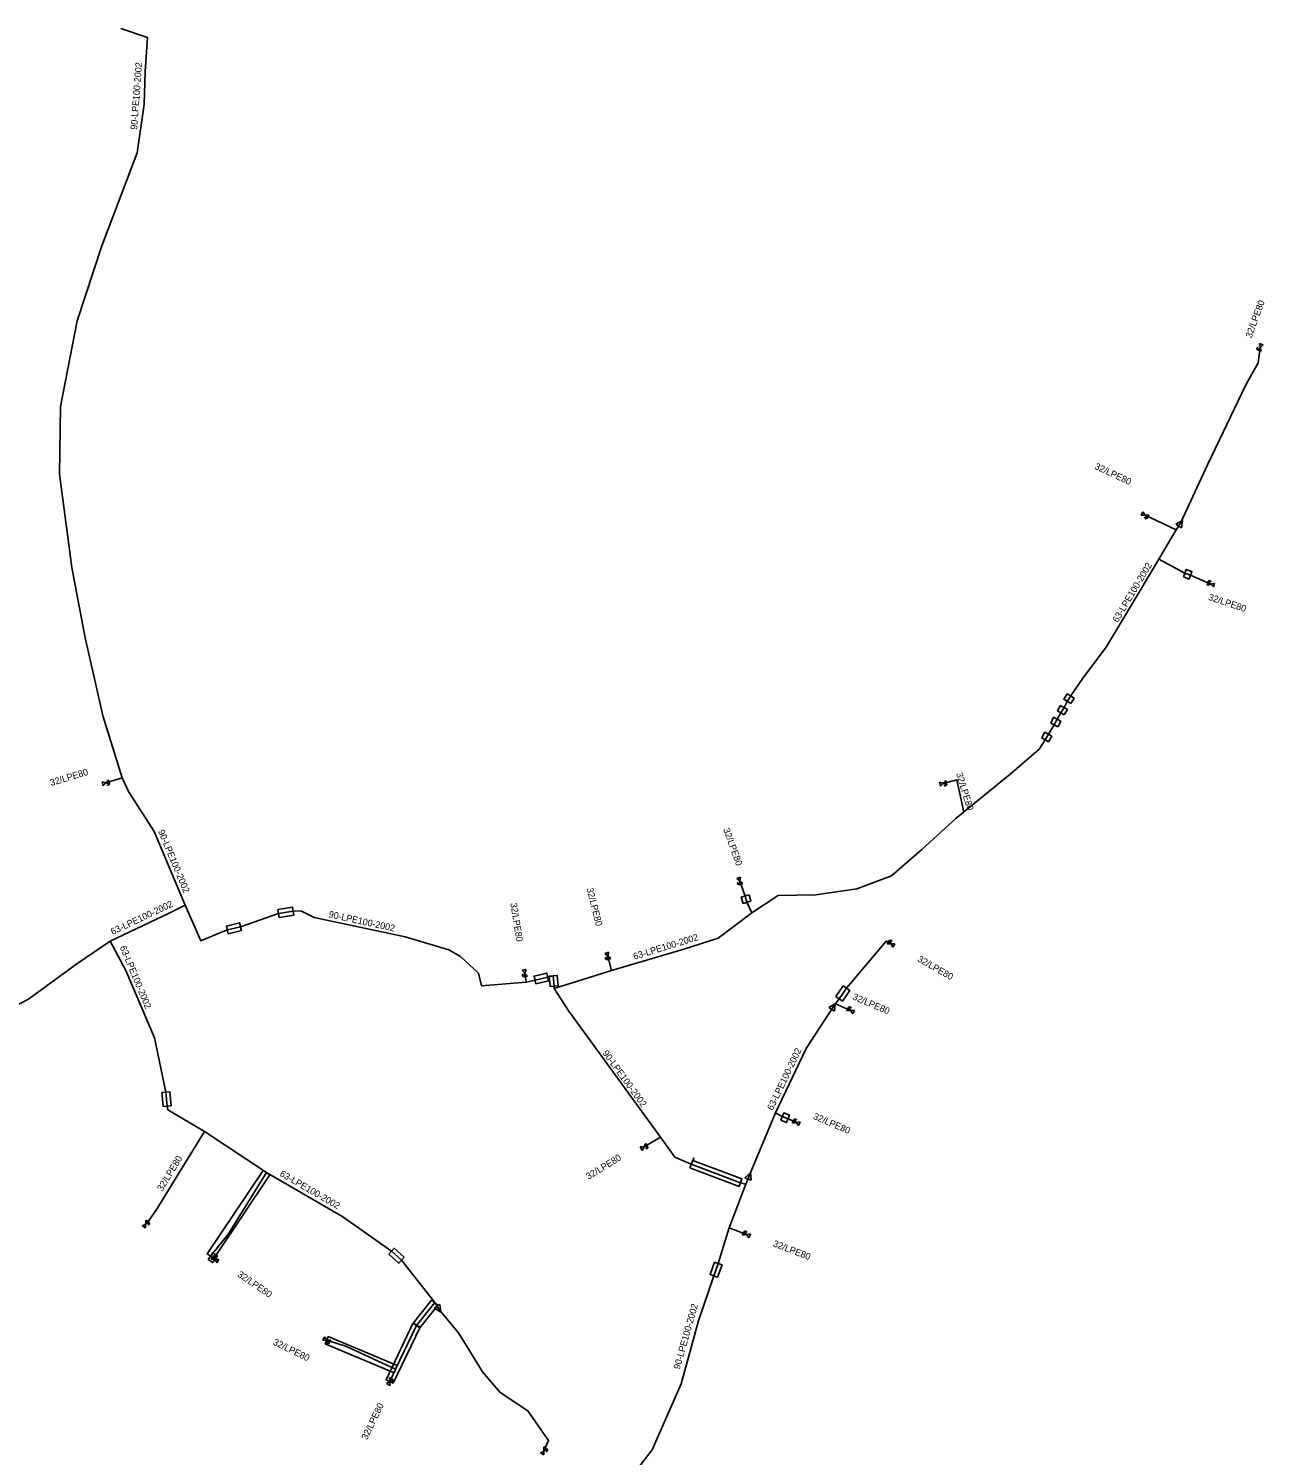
# Model space of a CAD drawing. Extents: x -787723 to -786204, y -1153846 to -1152384.
# Drawn here: x -787326.5 to -787141.5, y -1152598 to -1152384.4 of the extents above; entities that cross this region are included whole.
import ezdxf

# ---------------------------------------------------------------- set-up
doc = ezdxf.new("R2010")
doc.units = 0
for name, color, linetype in [('Vrstva 1', 7, 'Continuous'), ('Vrstva 21', 7, 'Continuous'), ('Vrstva 26', 7, 'Continuous'), ('Vrstva 28', 7, 'Continuous'), ('Vrstva 29', 7, 'Continuous'), ('Vrstva 31', 7, 'Continuous'), ('Vrstva 32', 7, 'Continuous')]:
    doc.layers.add(name, color=color, linetype=linetype)

# ---------------------------------------------------------------- blocks, each defined once
blk = doc.blocks.new('DEC122')
at = {"layer": 'Vrstva 1'}
for p, q in [((-0.5, 0.5), (0.5, 0)), ((-0.5, -0.5), (-0.5, 0.5)), ((0.5, 0), (-0.5, -0.5))]:
    blk.add_line(p, q, dxfattribs=at)
blk = doc.blocks.new('DEC063-SN')
at = {"layer": 'Vrstva 1'}
for p, q in [((-0.5, -0.3), (0.5, 0.3)), ((0.5, -0.3), (-0.5, 0.3)), ((-0.5, 0.3), (-0.5, -0.3)), ((0.5, 0.3), (0.5, -0.3)), ((0.126, -0.318), (0.126, -0.458)), ((0.126, -0.384), (0.206, -0.384)), ((0.206, -0.458), (0.206, -0.318)), ((0.366, -0.458), (0.366, -0.318))]:
    blk.add_line(p, q, dxfattribs=at)
for points in [[(0.246, -0.318), (0.246, -0.418), (0.252, -0.438), (0.264, -0.451), (0.281, -0.458), (0.292, -0.458), (0.309, -0.451), (0.321, -0.438), (0.326, -0.418), (0.326, -0.318)], [(0.366, -0.318), (0.418, -0.318), (0.435, -0.325), (0.441, -0.331), (0.446, -0.344), (0.446, -0.364), (0.441, -0.378), (0.435, -0.384), (0.418, -0.391), (0.366, -0.391)]]:
    blk.add_lwpolyline(points, dxfattribs=at)
blk = doc.blocks.new('DEC127')
at = {"layer": 'Vrstva 1'}
for p, q in [((0, 0.56), (0, 0.99)), ((0, 0.42), (0, -0.01))]:
    blk.add_line(p, q, dxfattribs=at)
blk.add_lwpolyline([(-0.07, 0.82), (0, 0.99), (0.07, 0.82)], dxfattribs=at)
blk.add_circle((0, 0.49), 0.07, dxfattribs=at)

msp = doc.modelspace()

# ---------------------------------------------------------------- linework, layer by layer
at = {"layer": 'Vrstva 21'}
for points in [[(-787312.7, -1152384.39), (-787308.67, -1152385.71), (-787309.02, -1152390.81), (-787309.17, -1152395.72), (-787310.22, -1152403), (-787315.5, -1152416.92), (-787319.2, -1152428.14), (-787321.71, -1152440.99), (-787321.84, -1152451.12), (-787320.01, -1152465.07), (-787318.03, -1152475.61), (-787315.34, -1152487.46), (-787312.48, -1152496.57), (-787311.55, -1152498.63), (-787307.67, -1152504.59), (-787303.05, -1152515.65)], [(-787247.83, -1152528.13), (-787239.23, -1152525.41), (-787228.42, -1152522.22), (-787223.27, -1152520.58), (-787218.24, -1152516.77), (-787214.29, -1152514.17), (-787208.66, -1152514.07), (-787202.49, -1152513.21), (-787197.32, -1152511.24), (-787192.76, -1152507.3), (-787187.62, -1152502.62), (-787179.31, -1152495.84), (-787175.21, -1152492.27), (-787174.31, -1152490.89), (-787173.83, -1152490.04), (-787172.95, -1152488.64), (-787172.51, -1152487.79), (-787171.98, -1152486.85), (-787171.49, -1152486.05), (-787171, -1152485.12), (-787170.5, -1152484.33), (-787168.69, -1152481.67), (-787165.19, -1152477.03), (-787160.26, -1152468.77), (-787157.29, -1152463.84), (-787154.69, -1152459.44), (-787154.04, -1152458.46)], [(-787303.05, -1152515.65), (-787305.46, -1152516.84), (-787314.29, -1152521.02)], [(-787303.05, -1152515.65), (-787300.7, -1152520.98), (-787297.37, -1152519.59)], [(-787297.37, -1152519.59), (-787296.73, -1152519.33), (-787294.76, -1152518.85), (-787289.1, -1152516.88), (-787286.86, -1152516.52), (-787285.71, -1152516.47), (-787283.72, -1152517.48), (-787270.14, -1152520.39), (-787263.59, -1152522.31), (-787261.81, -1152523.34), (-787259.14, -1152525.8), (-787258.71, -1152527.69), (-787251.98, -1152527.14), (-787250.68, -1152526.84), (-787248.78, -1152526.39), (-787247.95, -1152526.22), (-787247.8, -1152527.77), (-787247.83, -1152528.13)], [(-787314.29, -1152521.02), (-787319.27, -1152524.41), (-787326.52, -1152529.72), (-787328.78, -1152530.89), (-787335.19, -1152530.22), (-787346.87, -1152528.71), (-787360.92, -1152526.63), (-787369.11, -1152525.66), (-787370.08, -1152525.59), (-787370.68, -1152525.5), (-787371.63, -1152525.47), (-787387.45, -1152524.45), (-787410.19, -1152522.66), (-787413.47, -1152522.96), (-787417.5, -1152523.41), (-787428.97, -1152521.44), (-787438.18, -1152520.66), (-787445.79, -1152519.98), (-787456.29, -1152517.94), (-787457.28, -1152517.79)], [(-787314.29, -1152521.02), (-787311.95, -1152525.4), (-787307.66, -1152535.48), (-787305.93, -1152543.65), (-787305.75, -1152545.7), (-787305.63, -1152546.28), (-787300.18, -1152549.52), (-787290.86, -1152555.67), (-787279.43, -1152562.29), (-787272.17, -1152567.45), (-787270.67, -1152568.78), (-787265.7, -1152575.13), (-787265.06, -1152576.12)], [(-787247.83, -1152528.13), (-787245.64, -1152531.52), (-787239.09, -1152540.48), (-787231.9, -1152550.34), (-787229.74, -1152553.38), (-787227.28, -1152554.41), (-787219.92, -1152557.18), (-787219.11, -1152557.41)], [(-787218.61, -1152556.15), (-787214.68, -1152546.74), (-787210.08, -1152537.11), (-787206.02, -1152530.8)], [(-787219.11, -1152557.41), (-787221.63, -1152563.94), (-787223.24, -1152569.27), (-787223.91, -1152571.11), (-787226.19, -1152577.85), (-787228.81, -1152587.31), (-787233.13, -1152597.19), (-787236.68, -1152601.75)], [(-787219.11, -1152557.41), (-787218.61, -1152556.15)]]:
    msp.add_lwpolyline(points, dxfattribs=at)
at = {"layer": 'Vrstva 29'}
for points in [[(-787153.62, -1152466.49), (-787153.2, -1152465.37), (-787152.35, -1152465.69), (-787152.77, -1152466.81)], [(-787170.49, -1152485.44), (-787171.51, -1152484.8), (-787171.01, -1152484.01), (-787169.99, -1152484.65)], [(-787171.47, -1152487.16), (-787172.49, -1152486.54), (-787172, -1152485.74), (-787170.98, -1152486.36)], [(-787172.42, -1152488.92), (-787173.48, -1152488.36), (-787173.04, -1152487.51), (-787171.98, -1152488.06)], [(-787173.79, -1152491.19), (-787174.83, -1152490.59), (-787174.35, -1152489.74), (-787173.31, -1152490.33)], [(-787219.8, -1152514.42), (-787218.64, -1152514.1), (-787218.38, -1152515.04), (-787219.54, -1152515.36)], [(-787289, -1152517.47), (-787289.2, -1152516.29), (-787286.96, -1152515.93), (-787286.76, -1152517.11)], [(-787296.59, -1152519.91), (-787296.87, -1152518.75), (-787294.9, -1152518.27), (-787294.62, -1152519.43)], [(-787250.54, -1152527.42), (-787250.82, -1152526.26), (-787248.92, -1152525.81), (-787248.64, -1152526.97)], [(-787248.55, -1152526.28), (-787247.35, -1152526.16), (-787247.2, -1152527.71), (-787248.4, -1152527.83)], [(-787204.65, -1152529.98), (-787205.63, -1152529.28), (-787204.53, -1152527.72), (-787203.55, -1152528.42)], [(-787306.53, -1152543.7), (-787305.33, -1152543.6), (-787305.15, -1152545.65), (-787306.35, -1152545.75)], [(-787213.9, -1152547.82), (-787213.44, -1152546.72), (-787212.56, -1152547.09), (-787213.02, -1152548.19)], [(-787291.36, -1152555.33), (-787290.36, -1152556), (-787298.76, -1152568.51), (-787299.76, -1152567.84)], [(-787227.49, -1152554.97), (-787227.07, -1152553.85), (-787219.71, -1152556.62), (-787220.13, -1152557.74)], [(-787299.6, -1152568.68), (-787298.92, -1152567.68), (-787298.23, -1152568.15), (-787298.91, -1152569.15)], [(-787272.57, -1152567.9), (-787271.77, -1152567), (-787270.27, -1152568.33), (-787271.07, -1152569.23)], [(-787223.8, -1152569.06), (-787222.68, -1152569.48), (-787223.35, -1152571.31), (-787224.47, -1152570.9)], [(-787267.94, -1152578.91), (-787268.88, -1152578.17), (-787266.17, -1152574.76), (-787265.23, -1152575.5)], [(-787271.89, -1152587.2), (-787272.97, -1152586.68), (-787268.95, -1152578.28), (-787267.87, -1152578.8)], [(-787282.09, -1152581.31), (-787281.63, -1152580.21), (-787271.31, -1152584.54), (-787271.77, -1152585.64)]]:
    msp.add_lwpolyline(points, close=True, dxfattribs=at)
at = {"layer": 'Vrstva 31'}
for points in [[(-787154.04, -1152458.46), (-787150.03, -1152449.73), (-787144.25, -1152437.73), (-787142.41, -1152434.44), (-787142.11, -1152432.13)], [(-787154.69, -1152459.44), (-787159.36, -1152457.24)], [(-787157.29, -1152463.84), (-787153.41, -1152465.93), (-787152.56, -1152466.25), (-787149.51, -1152467.56)], [(-787312.48, -1152496.57), (-787314.92, -1152497.31)], [(-787186.49, -1152501.7), (-787187.52, -1152496.89), (-787189.59, -1152497.4)], [(-787218.24, -1152516.77), (-787218.96, -1152515.2), (-787219.22, -1152514.26), (-787220.03, -1152512.02)], [(-787205.75, -1152530.44), (-787205.14, -1152529.63), (-787204.04, -1152528.07), (-787198.09, -1152521.01), (-787197.38, -1152521.42)], [(-787239.23, -1152525.41), (-787239.78, -1152523.25)], [(-787251.98, -1152527.14), (-787252.19, -1152525.81)], [(-787206.02, -1152530.8), (-787205.75, -1152530.44)], [(-787205.72, -1152530.41), (-787203.44, -1152531.39)], [(-787214.68, -1152546.74), (-787213.67, -1152547.27), (-787212.79, -1152547.64), (-787211.57, -1152548.16)], [(-787300.18, -1152549.52), (-787307.26, -1152561.04), (-787308.46, -1152562.79), (-787308.95, -1152563.37)], [(-787231.9, -1152550.34), (-787234.35, -1152551.83)], [(-787290.86, -1152555.67), (-787296.57, -1152564.82), (-787299.26, -1152568.18), (-787298.57, -1152568.65)], [(-787221.63, -1152563.94), (-787219.02, -1152564.95)], [(-787265.7, -1152575.13), (-787268.41, -1152578.54), (-787271.54, -1152585.08)], [(-787265.06, -1152576.12), (-787262.13, -1152579.65), (-787258.54, -1152585.52), (-787255.88, -1152588.59), (-787251.74, -1152591.32), (-787248.66, -1152595.79), (-787249.34, -1152597.33)], [(-787271.54, -1152585.09), (-787278.88, -1152581.72), (-787281.86, -1152580.76)], [(-787271.54, -1152585.08), (-787271.54, -1152585.09), (-787272.43, -1152586.94)]]:
    msp.add_lwpolyline(points, dxfattribs=at)

# ---------------------------------------------------------------- block references
at = {"layer": 'Vrstva 26'}
for p, rotation in [((-787154.04, -1152458.46), 56.44506392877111), ((-787206.02, -1152530.8), 57.241833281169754), ((-787218.61, -1152556.15), 68.35556389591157), ((-787265.06, -1152576.12), -57.11876110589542)]:
    msp.add_blockref('DEC122', p, dxfattribs=dict(at, rotation=rotation))
at = {"layer": 'Vrstva 28', "rotation": -21.020419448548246}
msp.add_blockref('DEC127', (-787227.28, -1152554.41), dxfattribs=at)
at = {"layer": 'Vrstva 32'}
for p, rotation in [((-787142.11, -1152432.13), -107.76398891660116), ((-787159.36, -1152457.24), -25.224752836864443), ((-787149.51, -1152467.56), 163.05394441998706), ((-787314.92, -1152497.31), 16.871433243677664), ((-787189.59, -1152497.4), 13.938558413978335), ((-787220.03, -1152512.02), -70.11964728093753), ((-787197.38, -1152521.42), 147.63930836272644), ((-787239.78, -1152523.25), -72.58878617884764), ((-787252.19, -1152525.81), -79.02512773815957), ((-787203.44, -1152531.39), 153.86424164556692), ((-787211.57, -1152548.16), 158.02622504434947), ((-787234.35, -1152551.83), 31.306430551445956), ((-787308.95, -1152563.37), 57.677608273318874), ((-787219.02, -1152564.95), 157.85208327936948), ((-787298.57, -1152568.65), 146.19840540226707), ((-787281.86, -1152580.76), -25.57514174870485), ((-787272.43, -1152586.94), 64.30867227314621), ((-787249.34, -1152597.33), 59.56567215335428)]:
    msp.add_blockref('DEC063-SN', p, dxfattribs=dict(at, rotation=rotation))

# ---------------------------------------------------------------- texts
at = {"layer": 'Vrstva 21'}
for s, rotation, p in [('90-LPE100-2002', 85.65, (-787310.25, -1152399.57)), ('63-LPE100-2002', 59.169, (-787163.45, -1152473.4)), ('90-LPE100-2002', 292.671, (-787307.14, -1152504.58)), ('63-LPE100-2002', 25.332, (-787313.91, -1152520.12)), ('90-LPE100-2002', 347.615, (-787281.64, -1152517.43)), ('63-LPE100-2002', 17.093, (-787235.81, -1152523.81)), ('63-LPE100-2002', 292.6, (-787312.86, -1152521.92)), ('90-LPE100-2002', 306.168, (-787240.65, -1152537.79)), ('63-LPE100-2002', 64.467, (-787215.1, -1152546.44)), ('63-LPE100-2002', 329.922, (-787288.99, -1152556.11)), ('90-LPE100-2002', 74.173, (-787229.02, -1152585.2))]:
    msp.add_text(s, height=1, rotation=rotation, dxfattribs=at).set_placement(p)
at = {"layer": 'Vrstva 31'}
for rotation, p in [(70.134, (-787143.42, -1152430.8)), (334.775, (-787167.01, -1152450.27)), (341.541, (-787149.97, -1152469.9)), (16.871, (-787323.11, -1152497.8)), (286.982, (-787187.66, -1152495.94)), (289.88, (-787222.52, -1152504.3)), (284.286, (-787242.97, -1152513.16)), (278.973, (-787254.37, -1152515.35)), (329.995, (-787193.53, -1152523.96)), (336.744, (-787203.25, -1152529.69)), (336.915, (-787209.14, -1152547.6)), (58.448, (-787306.49, -1152558.54)), (31.306, (-787242.68, -1152556.76)), (338.845, (-787215.14, -1152566.67)), (325.739, (-787295.32, -1152571.14)), (333.98, (-787290, -1152581.37)), (64.309, (-787275.82, -1152595.75))]:
    msp.add_text('32/LPE80', height=1, rotation=rotation, dxfattribs=at).set_placement(p)

doc.saveas('drawing.dxf')
